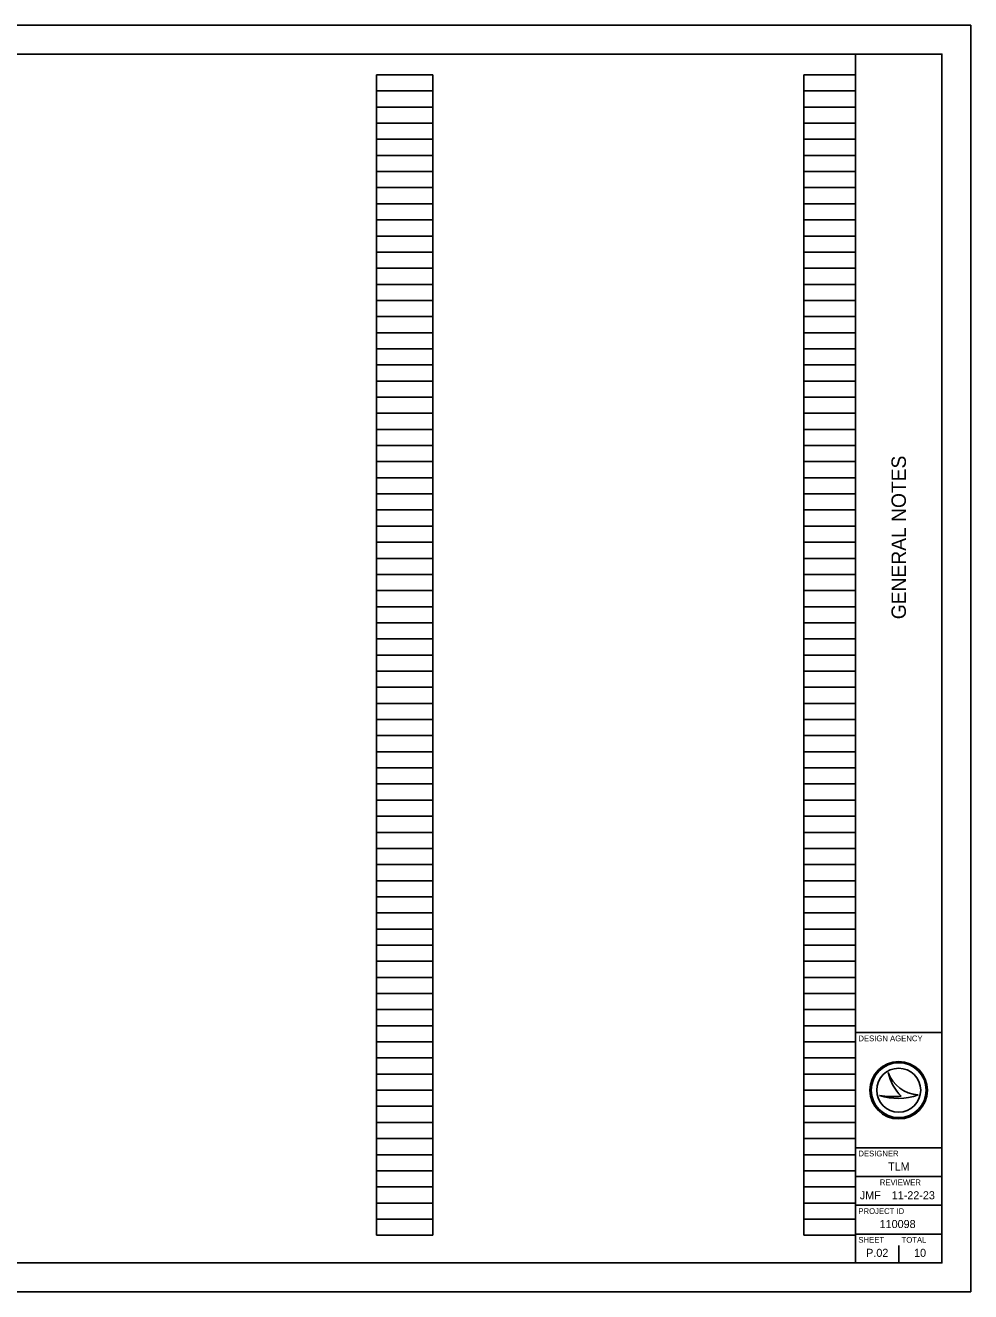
# Model space of a CAD drawing. Extents: x 0 to 34, y 0 to 22.
# Drawn here: x 17.58 to 34, y 0 to 22 of the extents above; entities that cross this region are included whole.
import ezdxf

# ---------------------------------------------------------------- set-up
doc = ezdxf.new("R2010")
doc.units = 0
for name, color, linetype in [('SH_Border', 7, 'Continuous'), ('SH_Cut_Line', 7, 'Continuous'), ('SH_Data', 7, 'Continuous')]:
    doc.layers.add(name, color=color, linetype=linetype)

msp = doc.modelspace()

# ---------------------------------------------------------------- linework, layer by layer
at = {"layer": 'SH_Border'}
for p, q in [((32, 0.5), (32, 21.5)), ((32, 4.5), (33.5, 4.5)), ((32, 2.5), (33.5, 2.5)), ((32, 2), (33.5, 2)), ((32, 1.5), (33.5, 1.5)), ((32, 1), (33.5, 1))]:
    msp.add_line(p, q, dxfattribs=at)
msp.add_lwpolyline([(1.5, 21.5), (33.5, 21.5), (33.5, 0.5), (1.5, 0.5)], close=True, dxfattribs=at)
at = {"layer": 'SH_Cut_Line'}
msp.add_lwpolyline([(0, 0), (34, 0), (34, 22), (0, 22)], close=True, dxfattribs=at)
at = {"layer": 'SH_Data'}
for p, q in [((23.68, 0.98), (23.68, 21.14)), ((23.68, 21.14), (24.66, 21.14)), ((24.66, 0.98), (24.66, 21.14)), ((31.1, 0.98), (31.1, 21.14)), ((31.1, 21.14), (32, 21.14)), ((32, 0.98), (32, 21.14)), ((23.68, 20.86), (24.66, 20.86)), ((31.1, 20.86), (32, 20.86)), ((23.68, 20.58), (24.66, 20.58)), ((31.1, 20.58), (32, 20.58)), ((23.68, 20.3), (24.66, 20.3)), ((31.1, 20.3), (32, 20.3)), ((23.68, 20.02), (24.66, 20.02)), ((31.1, 20.02), (32, 20.02)), ((23.68, 19.74), (24.66, 19.74)), ((31.1, 19.74), (32, 19.74)), ((23.68, 19.46), (24.66, 19.46)), ((31.1, 19.46), (32, 19.46)), ((23.68, 19.18), (24.66, 19.18)), ((31.1, 19.18), (32, 19.18)), ((23.68, 18.9), (24.66, 18.9)), ((31.1, 18.9), (32, 18.9)), ((23.68, 18.62), (24.66, 18.62)), ((31.1, 18.62), (32, 18.62)), ((23.68, 18.34), (24.66, 18.34)), ((31.1, 18.34), (32, 18.34)), ((23.68, 18.06), (24.66, 18.06)), ((31.1, 18.06), (32, 18.06)), ((23.68, 17.78), (24.66, 17.78)), ((31.1, 17.78), (32, 17.78)), ((23.68, 17.5), (24.66, 17.5)), ((31.1, 17.5), (32, 17.5)), ((23.68, 17.22), (24.66, 17.22)), ((31.1, 17.22), (32, 17.22)), ((23.68, 16.94), (24.66, 16.94)), ((31.1, 16.94), (32, 16.94)), ((23.68, 16.66), (24.66, 16.66)), ((31.1, 16.66), (32, 16.66)), ((23.68, 16.38), (24.66, 16.38)), ((31.1, 16.38), (32, 16.38)), ((23.68, 16.1), (24.66, 16.1)), ((31.1, 16.1), (32, 16.1)), ((23.68, 15.82), (24.66, 15.82)), ((31.1, 15.82), (32, 15.82)), ((23.68, 15.54), (24.66, 15.54)), ((31.1, 15.54), (32, 15.54)), ((23.68, 15.26), (24.66, 15.26)), ((31.1, 15.26), (32, 15.26)), ((23.68, 14.98), (24.66, 14.98)), ((31.1, 14.98), (32, 14.98)), ((23.68, 14.7), (24.66, 14.7)), ((31.1, 14.7), (32, 14.7)), ((23.68, 14.42), (24.66, 14.42)), ((31.1, 14.42), (32, 14.42)), ((23.68, 14.14), (24.66, 14.14)), ((31.1, 14.14), (32, 14.14)), ((23.68, 13.86), (24.66, 13.86)), ((31.1, 13.86), (32, 13.86)), ((23.68, 13.58), (24.66, 13.58)), ((31.1, 13.58), (32, 13.58)), ((23.68, 13.3), (24.66, 13.3)), ((31.1, 13.3), (32, 13.3)), ((23.68, 13.02), (24.66, 13.02)), ((31.1, 13.02), (32, 13.02)), ((23.68, 12.74), (24.66, 12.74)), ((31.1, 12.74), (32, 12.74)), ((23.68, 12.46), (24.66, 12.46)), ((31.1, 12.46), (32, 12.46)), ((23.68, 12.18), (24.66, 12.18)), ((31.1, 12.18), (32, 12.18)), ((23.68, 11.9), (24.66, 11.9)), ((31.1, 11.9), (32, 11.9)), ((23.68, 11.62), (24.66, 11.62)), ((31.1, 11.62), (32, 11.62)), ((23.68, 11.34), (24.66, 11.34)), ((31.1, 11.34), (32, 11.34)), ((23.68, 11.06), (24.66, 11.06)), ((31.1, 11.06), (32, 11.06)), ((23.68, 10.78), (24.66, 10.78)), ((31.1, 10.78), (32, 10.78)), ((23.68, 10.5), (24.66, 10.5)), ((31.1, 10.5), (32, 10.5)), ((23.68, 10.22), (24.66, 10.22)), ((31.1, 10.22), (32, 10.22)), ((23.68, 9.94), (24.66, 9.94)), ((31.1, 9.94), (32, 9.94)), ((23.68, 9.66), (24.66, 9.66)), ((31.1, 9.66), (32, 9.66)), ((23.68, 9.38), (24.66, 9.38)), ((31.1, 9.38), (32, 9.38)), ((23.68, 9.1), (24.66, 9.1)), ((31.1, 9.1), (32, 9.1)), ((23.68, 8.82), (24.66, 8.82)), ((31.1, 8.82), (32, 8.82)), ((23.68, 8.54), (24.66, 8.54)), ((31.1, 8.54), (32, 8.54)), ((23.68, 8.26), (24.66, 8.26)), ((31.1, 8.26), (32, 8.26)), ((23.68, 7.98), (24.66, 7.98)), ((31.1, 7.98), (32, 7.98)), ((23.68, 7.7), (24.66, 7.7)), ((31.1, 7.7), (32, 7.7)), ((23.68, 7.42), (24.66, 7.42)), ((31.1, 7.42), (32, 7.42)), ((23.68, 7.14), (24.66, 7.14)), ((31.1, 7.14), (32, 7.14)), ((23.68, 6.86), (24.66, 6.86)), ((31.1, 6.86), (32, 6.86)), ((23.68, 6.58), (24.66, 6.58)), ((31.1, 6.58), (32, 6.58)), ((23.68, 6.3), (24.66, 6.3)), ((31.1, 6.3), (32, 6.3)), ((23.68, 6.02), (24.66, 6.02)), ((31.1, 6.02), (32, 6.02)), ((23.68, 5.74), (24.66, 5.74)), ((31.1, 5.74), (32, 5.74)), ((23.68, 5.46), (24.66, 5.46)), ((31.1, 5.46), (32, 5.46)), ((23.68, 5.18), (24.66, 5.18)), ((31.1, 5.18), (32, 5.18)), ((23.68, 4.9), (24.66, 4.9)), ((31.1, 4.9), (32, 4.9)), ((23.68, 4.62), (24.66, 4.62)), ((31.1, 4.62), (32, 4.62)), ((23.68, 4.34), (24.66, 4.34)), ((31.1, 4.34), (32, 4.34)), ((23.68, 4.06), (24.66, 4.06)), ((31.1, 4.06), (32, 4.06)), ((23.68, 3.78), (24.66, 3.78)), ((31.1, 3.78), (32, 3.78)), ((32.567, 3.81), (32.567, 3.81)), ((23.68, 3.5), (24.66, 3.5)), ((31.1, 3.5), (32, 3.5)), ((32.417, 3.41), (32.417, 3.41)), ((32.75, 3.5), (32.75, 3.5)), ((33.087, 3.419), (33.087, 3.419)), ((23.68, 3.22), (24.66, 3.22)), ((31.1, 3.22), (32, 3.22)), ((23.68, 2.94), (24.66, 2.94)), ((31.1, 2.94), (32, 2.94)), ((23.68, 2.66), (24.66, 2.66)), ((31.1, 2.66), (32, 2.66)), ((23.68, 2.38), (24.66, 2.38)), ((31.1, 2.38), (32, 2.38)), ((23.68, 2.1), (24.66, 2.1)), ((31.1, 2.1), (32, 2.1)), ((23.68, 1.82), (24.66, 1.82)), ((31.1, 1.82), (32, 1.82)), ((23.68, 1.54), (24.66, 1.54)), ((31.1, 1.54), (32, 1.54)), ((23.68, 1.26), (24.66, 1.26)), ((31.1, 1.26), (32, 1.26)), ((23.68, 0.98), (24.66, 0.98)), ((31.1, 0.98), (32, 0.98)), ((32.375, 0.675), (32.375, 0.675)), ((32.75, 0.5), (32.75, 0.8))]:
    msp.add_line(p, q, dxfattribs=at)
for radius in [0.5, 0.477, 0.477, 0.382]:
    msp.add_circle((32.75, 3.5), radius, dxfattribs=at)
for centre, radius, start, end in [((33.116, 3.998), 0.58, 198.9257, 198.9319), ((33.347, 3.97), 0.796, 191.6379, 191.6421), ((33.116, 3.998), 0.58, 198.9319, 267.1657), ((33.347, 3.97), 0.796, 191.6421, 226.0947), ((32.739, 4.37), 1.013, 251.4576, 290.0832), ((32.648, 4.654), 1.266, 259.4964, 259.4995), ((32.739, 4.37), 1.013, 251.4527, 251.4576), ((32.648, 4.654), 1.266, 259.4995, 276.6672)]:
    msp.add_arc(centre, radius, start, end, dxfattribs=at)

# ---------------------------------------------------------------- texts
msp.add_text('GENERAL NOTES', height=0.25, rotation=90, dxfattribs=at).set_placement((32.875, 11.682))
for s, height, p in [('DESIGN AGENCY', 0.1, (32.05, 4.35)), ('DESIGNER', 0.1, (32.05, 2.35)), ('TLM', 0.14, (32.565, 2.105)), ('REVIEWER', 0.1, (32.422, 1.85)), ('JMF', 0.14, (32.075, 1.605)), ('11-22-23', 0.14, (32.629, 1.605)), ('PROJECT ID', 0.1, (32.05, 1.35)), ('110098', 0.14, (32.419, 1.105)), ('SHEET', 0.1, (32.05, 0.85)), ('TOTAL', 0.1, (32.8, 0.85)), ('P.02', 0.14, (32.185, 0.605)), ('10', 0.14, (33.017, 0.605))]:
    msp.add_text(s, height=height, dxfattribs=at).set_placement(p)

doc.saveas('drawing.dxf')
